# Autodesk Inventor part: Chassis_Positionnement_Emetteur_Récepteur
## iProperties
Created: 2008-12
Part Number: Chassis_Positionnement_Emetteur_Récepteur
Document SubType Name: Sheet Metal
Designer: claivier
Author: claivier
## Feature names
1. Perçage1 [Hole]
2. Perçage2 [Hole]
3. Miroir1 [Mirror]
4. Perçage3 [Hole]
5. Plaque1
6. Pli1
7. Couper1
